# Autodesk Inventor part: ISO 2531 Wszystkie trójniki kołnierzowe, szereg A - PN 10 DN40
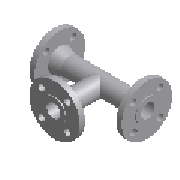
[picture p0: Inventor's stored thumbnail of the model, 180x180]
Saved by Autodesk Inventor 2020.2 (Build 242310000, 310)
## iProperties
Manager: www.cadconsulting.pl
Company: Fabian Stasiak CAD Consulting
NAME: PIPING: ISO 2531 All Flanged Tee Series A - PN 10
DATA: <meta><inlinegroups number="1" deflen="28"></inlinegroups><connections number="3"></connections><angles><a>3.14159265358979</a><a>1.5707963267949</a></angles></
IsCustomPart: 0
Created: 2014-02
Part Number: ISO 2531 Wszystkie trójniki kołnierzowe, szereg A - PN 10 DN40
Material: Żeliwo sferoidalne
Description: Rury, łączniki, akcesoria z żeliwa sferoidalnego i ich złącza do zastosowań w instalacjach wodnych lub gazowych - Wszystkie trójniki kołnierzowe, szereg A - PN
Document SubType Name: Modeling
Standard: ISO 2531
Designer: F.Stasiak
Standard Revision: Fifth edition 1998-08-15
Standards Organization: ISO
Language: pl-PL
Size Designation: DN40
Categories: <MemberInstance><Categories><Category DisplayName="Rury cienko- i grubościenne" InternalName="4347fa0f-2144-441d-94cd-e3e15c92b736" Mnemonic="TUBEANDPIPE"><Cate
Density: 7.15 g/cm^3
Appearance: Ciemnoszary
Catalog Web Link: www.expertbooks.pl
Author: F.Stasiak
Subject: Zbiór ćwiczeń. Autodesk Inventor 2020. Kurs Professional
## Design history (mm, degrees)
sketch "Sketch1"
  geometry: L1 (0, 20)-(280, 20); L2 (280, 20)-(280, 0); L3 (280, 0)-(0, 0); L4 (0, 0)-(0, 20); L5 (0, 20)-(0, 35); L6 (0, 35)-(3, 35); L7 (3, 35)-(3, 75); L8 (3, 75)-(19, 75); L9 (19, 75)-(19, 35); L10 (48.856, 27)-(231.144, 27); L11 (140, 0)-(140, 27); L12 (261, 75)-(261, 35); L13 (277, 75)-(261, 75); L14 (277, 35)-(277, 75); L15 (280, 35)-(277, 35); L16 (280, 20)-(280, 35); L17 (19, 35)-(48.856, 27); L18 (19, 35)-(1.5, 35); L19 (261, 35)-(231.144, 27); L20 (19, 35)-(261, 35); 1 further point
  constraints: 40 end point, 6 parallel, 4 symmetric about line, 3 midpoint, 3 perpendicular, 2 collinear, 2 horizontal, 1 coincident, 5 other
  dimensions: "d0" = 40 diameter of L1 L3 (= ID); "d1" = 7 distance between parallel lines of L1 L10 (= e1); "d2" = 70 diameter of L6 L3 (= N3); "d3" = 150 diameter of L8 L3 (= D); "d4" = 3 distance of L5.end L6.end; "d5" = 19 distance between parallel lines of L9 L5 (= C7); "d6" = 140 distance between parallel lines of L2 L11 (= 0.5 x L); "d24" = 15 deg angle of L10 L17; "d25" = 15 deg angle of L10 L19
revolve "Revolution1" sketch "Sketch1" stored, may be unused: angle "d7" = 90 deg
workplane "Work Plane1"
sketch "Sketch2"
  geometry: L1 (280, 0)-(0, 0) reference; L2 (140, 0)-(140, 27) reference; C1 r 27 at (140, 0); C2 r 20 at (140, 0)
  constraints: 2 centre point, 2 coincident, 1 concentric
  dimensions: "d9" = 40 diameter of C2 (= ID2); "d10" = 54 diameter of C1 (= ID2 + 2 x e2)
extrude "Extrusion1" join sketch "Sketch2" stored distance "d11" = 25.4; taper "d12" = 0 deg
extrude "Extrusion2" cut sketch "Sketch2" stored distance "d13" = 25.4; taper "d14" = 0 deg
sketch "Sketch3"
  geometry: L1 (-120, 121)-(-65, 121); L2 (-65, 121)-(-65, 137); L3 (-65, 137)-(-105, 137); L4 (-105, 137)-(-105, 140); L5 (-105, 140)-(-120, 140); L6 (-120, 140)-(-120, 121); L7 (-120, 121)-(-140, 121); L8 (-140, 121)-(-140, 140); L9 (-140, 140)-(-120, 140); L10 (-160, 140)-(-120, 140) reference; 1 further point
  constraints: 18 end point, 5 parallel, 3 perpendicular, 1 coincident, 1 horizontal
  dimensions: "d15" = 70 diameter of L4 L8 (= N32); "d16" = 3 distance between parallel lines of L3 L5; "d17" = 19 distance between parallel lines of L1 L5 (= C72); "d18" = 150 diameter of L2 L8 (= D2)
revolve "Revolution2" sketch "Sketch3" stored, may be unused: angle "d20" = 90 deg
sketch "Sketch7"
  geometry: L1 (38.891, 38.891)-(0, 0); L2 (0, 0)-(0, 55); C1 r 35 at (0, 0) reference; C2 r 9.5 at (38.891, 38.891); A1 r 55 centre (0, 0) between (38.891, 38.891) and (0, 55)
  constraints: 4 end point, 2 centre point, 2 point on circle, 1 coincident, 1 vertical
  dimensions: "d36" = 45 deg angle of L1 L2 (computed from NU); "d37" = 19 diameter of C2 (= L2); "d39" = 110 diameter of A1 (= K1)
extrude "Extrusion4" cut sketch "Sketch7" taper "d40" = 0 deg; stored distance "d46" = 10
pattern_circular "Circular Pattern1" dims angle "d21" = 360 deg
sketch "Sketch5"
  geometry: L1 (-215, 121)-(-65, 121) reference; L2 (-167, 121)-(-167, 27) reference; L3 (-113, 121)-(-113, 27) reference; L4 (-167, 121)-(-175, 121); L5 (-175, 121)-(-167, 91.144); L6 (-167, 91.144)-(-167, 121); L7 (-140, 121)-(-140, 27); L8 (-167, 27)-(-113, 27); L9 (-113, 121)-(-105, 121); L10 (-105, 121)-(-113, 91.144); L11 (-113, 91.144)-(-113, 121)
  constraints: 16 end point, 3 perpendicular, 3 symmetric about line, 2 collinear, 2 midpoint, 1 parallel, 3 other
  dimensions: "d27" = 70 diameter of L4.end L7 (= N32); "d28" = 15 deg angle of L2 L5
revolve "Revolution4" sketch "Sketch5" stored, may be unused: angle "d35" = 90 deg
sketch "Sketch6"
  geometry: L1 (38.891, -38.891)-(-38.891, 38.891); L2 (0, 0)-(55, 0); C1 r 75 at (0, 0) reference; C2 r 35 at (0, 0) reference; C3 r 9.5 at (38.891, -38.891); A1 r 55 centre (0, 0) between (38.891, -38.891) and (-38.891, 38.891)
  constraints: 4 end point, 3 point on circle, 2 centre point, 2 coincident, 1 concentric, 1 horizontal, 1 midpoint
  dimensions: "d30" = 110 diameter of A1 (= K12); "d31" = 19 diameter of C3 (= L22); "d42" = 45 deg angle of L2 L1 (computed from NU2)
extrude "Extrusion3" cut sketch "Sketch6" taper "d32" = 0 deg; stored distance "d38" = 10
pattern_circular "Circular Pattern3" dims angle "d34" = 360 deg
sketch "Sketch8"
  geometry: L1 (0, 0)-(0, 55); L2 (0, 0)-(38.891, 38.891); C1 r 35 at (0, 0) reference; C2 r 9.5 at (38.891, 38.891); A1 r 55 centre (0, 0) between (0, 55) and (38.891, 38.891); 1 further point
  constraints: 4 end point, 2 centre point, 2 coincident, 2 point on circle, 1 vertical
  dimensions: "d49" = 110 diameter of A1 (= K1); "d50" = 45 deg angle of L2 L1 (computed from NU); "d51" = 19 diameter of C2 (= L2)
extrude "Extrusion5" cut sketch "Sketch8" stored distance "d52" = 10; taper "d53" = 0 deg
pattern_circular "Circular Pattern4" dims angle "d55" = 360 deg
workaxis "Work Axis5"
workpoint "Work Point4"
workaxis "Work Axis6"
workpoint "Work Point5"
workaxis "Work Axis7"
workpoint "Work Point6"
body "Solid1"
other parameters: "D" = 150 [user parameter; used in 1 equation term], "C7" = 19 [user parameter; used in 1 equation term], "e1" = 7 [user parameter; used in 1 equation term], "ID" = 40 [user parameter; used in 1 equation term], "N3" = 70 [user parameter; used in 1 equation term], "K1" = 110 [user parameter; used in 2 equation terms], "L2" = 19 [user parameter; used in 2 equation terms], "D2" = 150 [user parameter; used in 1 equation term], "C72" = 19 [user parameter; used in 1 equation term], "ID2" = 40 [user parameter; used in 2 equation terms], "N32" = 70 [user parameter; used in 2 equation terms], "e2" = 7 [user parameter; used in 1 equation term], "K12" = 110 [user parameter; used in 1 equation term], "L22" = 19 [user parameter; used in 1 equation term], "Size_Designation" = 12.345 [user parameter]
